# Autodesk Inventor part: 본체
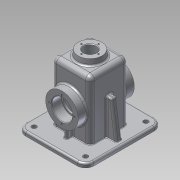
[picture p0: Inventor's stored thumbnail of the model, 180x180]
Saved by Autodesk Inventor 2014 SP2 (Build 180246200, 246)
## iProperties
Created: 2016-08
Part Number: 본체
Material: 알루미늄 6061
Document SubType Name: Modeling
Designer: user
Density: 2.71 g/cm^3
Appearance: 알루미늄 - 평지
Author: user
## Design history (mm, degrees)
sketch "스케치1"
  geometry: L1 (-57.5, -65)-(57.5, -65); L2 (57.5, -65)-(57.5, 65); L3 (57.5, 65)-(-57.5, 65); L4 (-57.5, 65)-(-57.5, -65); L5 (-57.5, -65)-(57.5, 65); L6 (57.5, -65)-(-57.5, 65); 1 further point
  constraints: 12 end point, 2 midpoint, 2 parallel, 1 horizontal, 1 perpendicular
  dimensions: "d0" = 115 distance of L3.end L2.end; "d1" = 130 distance of L2.end L1.end
extrude "돌출1" new body sketch "스케치1" distance "d2" = 10; taper "d3" = 0 deg
sketch "스케치2"
  geometry: L1 (-32.5, 32.5)-(32.5, 32.5); L2 (32.5, 32.5)-(32.5, -32.5); L3 (32.5, -32.5)-(-32.5, -32.5); L4 (-32.5, -32.5)-(-32.5, 32.5); L5 (-32.5, 32.5)-(32.5, -32.5); L6 (32.5, 32.5)-(-32.5, -32.5); 1 further point
  constraints: 12 end point, 2 midpoint, 2 parallel, 1 horizontal, 1 perpendicular
  dimensions: "d4" = 65 distance of L2.end L3.end; "d5" = 65 distance of L1.end L2.end
extrude "돌출2" join sketch "스케치2" distance "d6" = 100; taper "d7" = 0 deg
fillet "모깎기1" dims "d11" = 8
fillet "모깎기2" dims "d12" = 8
feature "쉘1" dims "d8" = 5
sketch "스케치4"
  geometry: L1 (25, 84.5)-(25, 35.5) reference; L2 (77, 87.5)-(28, 87.5) reference; L3 (80, 35.5)-(80, 84.5) reference; L4 (28, 32.5)-(77, 32.5) reference; L5 (105, 0)-(0, 0) reference; L6 (105, 120)-(105, 0) reference; L7 (0, 120)-(105, 120) reference; L8 (0, 0)-(0, 120) reference; A1 r 3 centre (28, 84.5) between (28, 87.5) and (25, 84.5) reference; A2 r 3 centre (77, 84.5) between (80, 84.5) and (77, 87.5) reference; A3 r 3 centre (77, 35.5) between (77, 32.5) and (80, 35.5) reference; A4 r 3 centre (28, 35.5) between (25, 35.5) and (28, 32.5) reference; 1 further point
extrude "돌출3" join sketch "스케치4" distance "d9" = 5; taper "d10" = 0 deg
node "작업 평면1"
sketch "스케치6"
  geometry: 1 further point
sketch "스케치7"
  geometry: C1 r 20 at (0, 0); 1 further point
  constraints: 1 centre point, 1 coincident
  dimensions: "d14" = 40 diameter of C1
extrude "돌출4" join sketch "스케치7" stored distance "d15" = 5; taper "d16" = 0 deg
feature "면 기울기1" dims angle "d17" = 7 deg
node "작업 평면2"
sketch "스케치8"
  geometry: L1 (-57.5, 0)-(57.5, 0) reference; C1 r 27.5 at (0, 55); 2 further points
  constraints: 1 centre point, 1 midpoint, 1 vertical alignment
  dimensions: "d19" = 55 diameter of C1; "d20" = 55 distance from line of L1 C1.centre
extrude "돌출5" join sketch "스케치8" stored distance "d21" = 15; taper "d22" = 0 deg
sketch "스케치9"
  geometry: L1 (47.5, 27.5)-(32.5, 27.5) reference; L2 (27.5, 102)-(27.5, 0) reference; L3 (32.5, 10)-(32.5, 42.51) reference; L4 (-65, 10)-(65, 10) reference; L5 (42.5, 27.5)-(42.5, 10); 1 further point
  constraints: 2 end point, 2 point on line, 1 perpendicular
  dimensions: "d23" = 15 distance between parallel lines of L2 L5
feature "리브1" sketch "스케치9" dims "d24" = 1, "d25" = 6, "d26" = 0, "d27" = 0, "d28" = 1, "d29" = 1
sketch "스케치10"
  geometry: L1 (-32.5, 10)-(-32.5, 102) reference; L2 (57.5, 10)-(-57.5, 10) reference; L3 (-49.5, 10)-(-41.068, 70); L4 (-41.068, 70)-(-32.5, 70); L5 (-57.5, 0)-(-57.5, 10) reference; L6 (57.5, 0)-(-57.5, 0) reference; 1 further point
  constraints: 4 end point, 2 point on line, 1 parallel
  dimensions: "d30" = 8 deg angle of L5 L3; "d31" = 8 distance of L3.start L2.end; "d32" = 70 distance between parallel lines of L6 L4
extrude "돌출6" join sketch "스케치10" stored distance "d33" = 10; taper "d34" = 0 deg
sketch "스케치11"
  geometry: C1 r 27.5 at (0, 0) reference; C2 r 15 at (0, 0); 1 further point
  constraints: 1 centre point, 1 coincident
  dimensions: "d35" = 30 diameter of C2
extrude "돌출7" cut sketch "스케치11" stored distance "d36" = 10; taper "d37" = 0 deg
sketch "스케치12"
  geometry: C1 r 15 at (0, 0) reference; C2 r 17.5 at (0, 0); 1 further point
  constraints: 1 centre point, 1 coincident
  dimensions: "d38" = 35 diameter of C2
extrude "돌출8" cut sketch "스케치12" distance "d39" = 17; taper "d40" = 0 deg
sketch "스케치13"
  geometry: C1 r 27.5 at (0, 0) reference; 2 further points
  constraints: 1 vertical alignment
  dimensions: "d41" = 21 distance of C1.centre point (0, -21)
hole "구멍1" sketch "스케치13" at (0, -21) diameter "d42" = 3.242; stored, may be unused: countersink angle "d46" = 90 deg, drill point angle "d48" = 118 deg; dims "d43" = 8, "d44" = 4, "d45" = 2, "d47" = 10
sketch "스케치14"
  geometry: C1 r 10.5 at (0, 0); 1 further point
  constraints: 1 centre point, 1 coincident
  dimensions: "d52" = 21 diameter of C1
extrude "돌출9" cut sketch "스케치14" stored distance "d53" = 17; taper "d54" = 0 deg
sketch "스케치15"
  geometry: C1 r 10.5 at (0, 0) reference; 2 further points
  constraints: 1 vertical alignment
  dimensions: "d55" = 14.5 distance of point (0, 0) point (0, -14.5)
hole "구멍2" sketch "스케치15" at (0, -14.5) diameter "d56" = 2.459; stored, may be unused: countersink angle "d60" = 90 deg, drill point angle "d62" = 118 deg; dims "d57" = 7, "d58" = 4, "d59" = 2, "d61" = 9
chamfer "모따기1" distance "d66" = 1; stored, may be unused: second distance "d67" = 2, angle "d68" = 45 deg
fillet "모깎기3" dims "d69" = 0.3
fillet "모깎기4" dims "d70" = 14
fillet "모깎기5" dims "d71" = 3
sketch "스케치16"
  geometry: L1 (-43.5, 65)-(43.5, 65) reference; L2 (-57.5, -51)-(-57.5, 51) reference; L3 (43.5, -65)-(-43.5, -65) reference; L4 (57.5, 51)-(57.5, -51) reference; L5 (-24.5, 27.5)-(24.5, 27.5) reference; L6 (27.5, 24.5)-(27.5, -24.5) reference; L7 (24.5, -27.5)-(-24.5, -27.5) reference; L8 (-27.5, -24.5)-(-27.5, 24.5) reference; L9 (52.5, 51)-(52.5, -51); L10 (43.5, -60)-(-43.5, -60); L11 (-52.5, -51)-(-52.5, 51); L12 (-43.5, 60)-(43.5, 60); A1 r 14 centre (43.5, 51) between (57.5, 51) and (43.5, 65) reference; A2 r 14 centre (-43.5, 51) between (-43.5, 65) and (-57.5, 51) reference; A3 r 14 centre (-43.5, -51) between (-57.5, -51) and (-43.5, -65) reference; A4 r 14 centre (43.5, -51) between (43.5, -65) and (57.5, -51) reference; A5 r 3 centre (24.5, 24.5) between (27.5, 24.5) and (24.5, 27.5) reference; A6 r 3 centre (24.5, -24.5) between (24.5, -27.5) and (27.5, -24.5) reference; A7 r 3 centre (-24.5, -24.5) between (-27.5, -24.5) and (-24.5, -27.5) reference; A8 r 3 centre (-24.5, 24.5) between (-24.5, 27.5) and (-27.5, 24.5) reference; A9 r 9 centre (43.5, 51) between (52.5, 51) and (43.5, 60); A10 r 9 centre (43.5, -51) between (43.5, -60) and (52.5, -51); A11 r 9 centre (-43.5, -51) between (-52.5, -51) and (-43.5, -60); A12 r 9 centre (-43.5, 51) between (-43.5, 60) and (-52.5, 51); 1 further point
  constraints: 8 end point, 8 point on circle, 4 centre point, 7 other
  dimensions: "d72" = 5 distance between parallel lines of L1 L12
extrude "돌출10" cut sketch "스케치16" distance "d73" = 3; taper "d74" = 0 deg
sketch "스케치17"
  geometry: C1 r 4 at (-43.5, -51); C2 r 4 at (43.5, -51); C3 r 4 at (43.5, 51); C4 r 4 at (-43.5, 51); A1 r 14 centre (-43.5, -51) between (-57.5, -51) and (-43.5, -65) reference; A2 r 14 centre (43.5, -51) between (43.5, -65) and (57.5, -51) reference; A3 r 14 centre (43.5, 51) between (57.5, 51) and (43.5, 65) reference; A4 r 14 centre (-43.5, 51) between (-43.5, 65) and (-57.5, 51) reference; 1 further point
  constraints: 4 centre point, 4 coincident
  dimensions: "d75" = 8 diameter of C1; "d78" = 8 diameter of C2; "d79" = 8 diameter of C3; "d80" = 8 diameter of C4
extrude "돌출12" cut sketch "스케치17" stored distance "d81" = 3; taper "d82" = 0 deg
sketch "스케치18"
  geometry: L1 (57, 0)-(57, 92) reference; L2 (44.5, -18)-(4.5, -18) reference; 2 further points
  constraints: 1 other
  dimensions: "d83" = 32.5 distance from line of L1 point (24.5, 8); "d84" = 26 distance from line of L2 point (24.5, 8)
feature "엠보싱1" sketch "스케치18" dims "d85" = 0.5, "d86" = 0
fillet "모깎기6" dims "d87" = 3
fillet "모깎기7" dims "d88" = 3
fillet "모깎기8" dims "d89" = 3
fillet "모깎기9" dims "d90" = 3
fillet "모깎기10" dims "d91" = 3
fillet "모깎기11" dims "d92" = 3
fillet "모깎기12" dims "d93" = 3
fillet "모깎기13" dims "d94" = 3
fillet "모깎기14" dims "d95" = 3
fillet "모깎기15" dims "d96" = 3
fillet "모깎기16" dims "d97" = 3
fillet "모깎기17" dims "d98" = 3
fillet "모깎기18" dims "d99" = 1
node "솔리드1"
mirror "대칭1"
mirror "대칭2"
mirror "대칭3"
mirror "대칭4"
pattern_circular "원형 패턴1" dims angle "d50" = 360 deg
mirror "대칭5"
pattern_circular "원형 패턴2" dims angle "d64" = 360 deg
node "투영된 루프1"
node "투영된 루프2"
other parameters: "d18" = 47.5
